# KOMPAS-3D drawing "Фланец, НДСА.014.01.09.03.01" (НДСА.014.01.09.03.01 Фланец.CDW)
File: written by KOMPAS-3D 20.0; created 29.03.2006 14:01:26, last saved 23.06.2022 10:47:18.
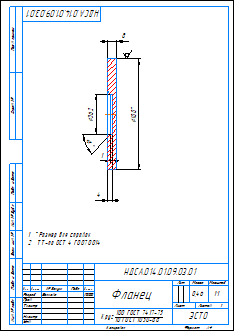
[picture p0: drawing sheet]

Sheet 1: A4, portrait

Document properties: Полное имя файла: НДСА.014.01.09.03.01 Фланец.m3d; 280830710273: <item xmlns="http://appius.ru/pdm" xmlns:xs="http://www.w3.org/2001/XMLSchema" xmlns:xsi="http://www.w3.org/2001/XMLSchema-instance" xsi:type="item">  <element xmlns:d2p1="http://v8.1c.ru/8.1/data/enterprise/current-config" xsi:type="d2p1:CatalogRef.aps_Элемен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; PLM_CDWXDTO: <item xmlns="http://appius.ru/pdm" xmlns:xs="http://www.w3.org/2001/XMLSchema" xmlns:xsi="http://www.w3.org/2001/XMLSchema-instance" xsi:type="item">  <element xmlns:d2p1="http://v8.1c.ru/8.1/data/enterprise/current-config" xsi:type="d2p1:CatalogRef.aps_Элемен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; Масса: 0.457022

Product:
- Part/product: Фланец  | designation НДСА.014.01.09.03.01
    Материал: Круг$d100 ГОСТ 7417-75;10 ГОСТ 1050-88$ (density 7856 kg/m3)
    Масса: 0.457022

Title block, sheet 1: Наименование: Фланец; designation: НДСА.014.01.09.03.01; Материал: Круг 100 ГОСТ 7417-75 10 ГОСТ 1050-88; Масса: 0,46; scale: 1:1; Количество листов документа: 1; organisation: ЭСТО; Форматы листов документа: A4; stored path: D:\Work-Kompas 6\УКРД.762.00.00.00.00 Верх.стойка гидр.подъём\УКРД.762.02.00.00.00 Опора\УКРД.762.02.00.00.02 Фланец.cdw; Разработал: Волкова; Разработал, date: 17.01.2020
Table, sheet 1:
  0;Material:VDE12371B5FDD453AAD3A0896F0FE5778;Sortament:V4344B293F9D843D7A912B88564B6ED05^SortamentEx:VA223890FA0E74A77B5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

Views: Спереди 1, Спереди, Разрез А-А
Referenced files in E:\НДСА.014.01.09.00.00 Верхняя стойка гидроподъемника\: НДСА.014.01.09.03.01 Фланец.m3d
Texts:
  НДСА.014.01.09.03.01 Фланец
Dimensions and other numbers on the sheet: 36,2; 8; 4; 100; 1; 1:1; 0,46; 17.01.2020

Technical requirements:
  1.  *Размер для справок.
  2.  Т.Т.-по ОСТ 4 ГО.070.014.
